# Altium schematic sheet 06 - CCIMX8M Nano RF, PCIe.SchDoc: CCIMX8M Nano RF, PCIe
size A3; PageSetup: Record=PageOptions¦CenterHorizontal=True¦CenterVertical=True¦PrintScale=0.70¦XCorrection=1.00¦YCorrection=1.00¦PrintKind=0¦BorderSize=5000000¦LeftOffset=0¦BottomOffset=0¦Orientation=2¦PaperLength=4200¦PaperWidth=2970¦Scale=100¦PaperSource=7¦PrintQuality=600¦MediaType=1¦DitherType=10¦PaperKind=A4¦PrintScaleMode=1; Author: Juan Anzola; SheetNumber: 6; SheetTotal: 21
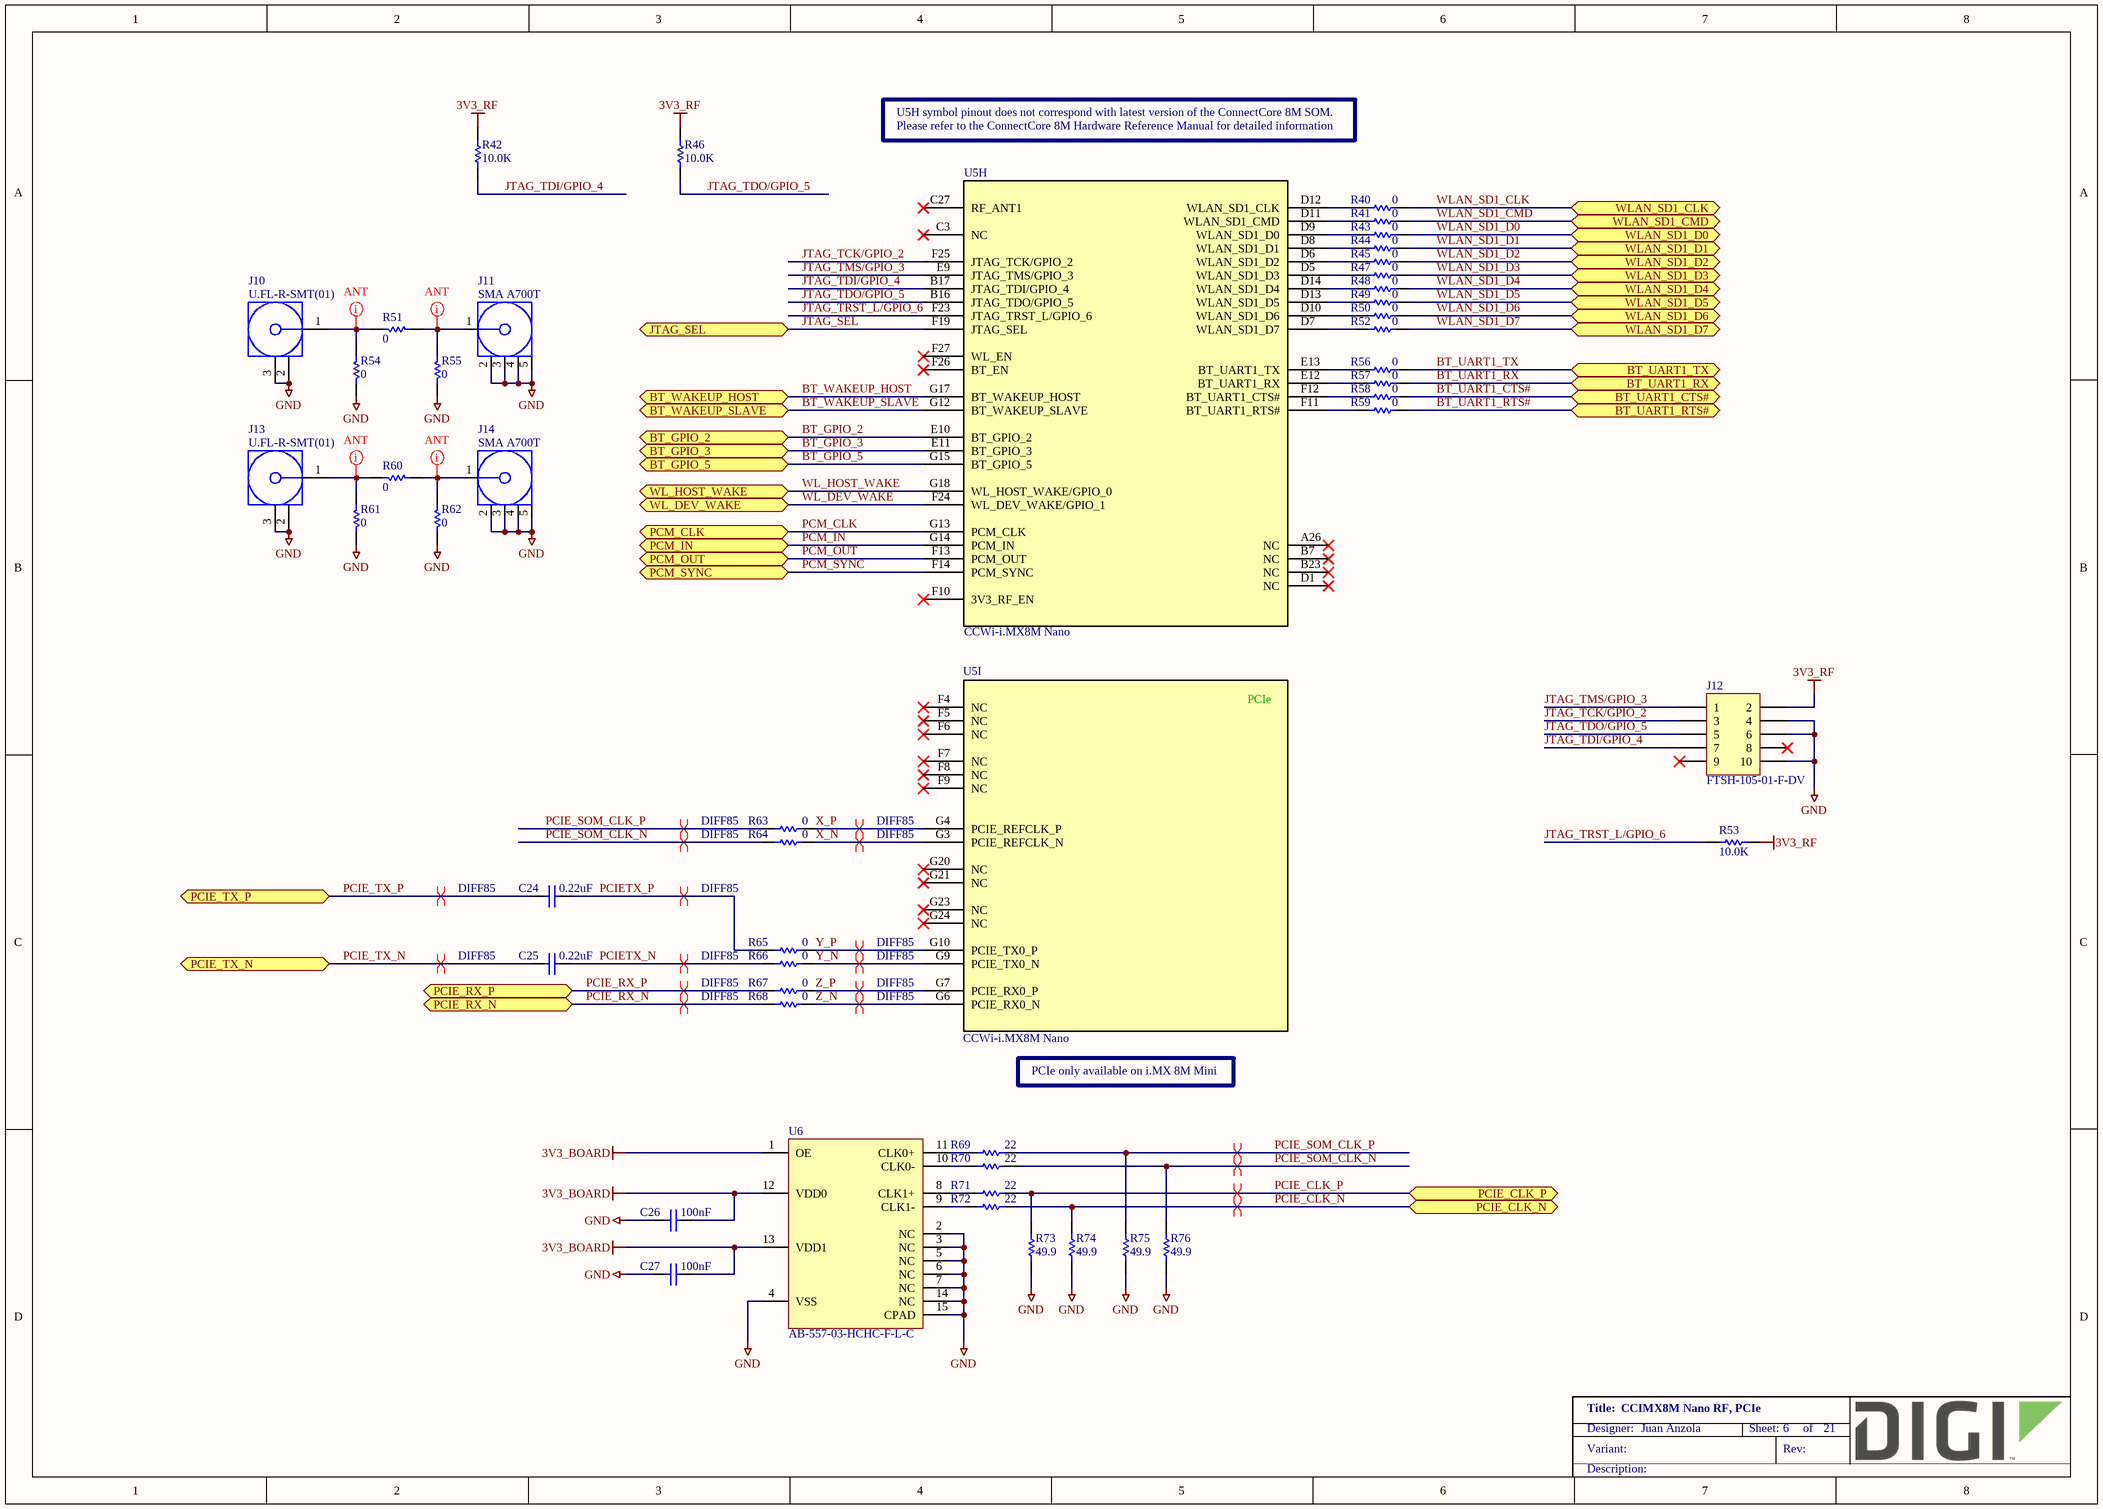
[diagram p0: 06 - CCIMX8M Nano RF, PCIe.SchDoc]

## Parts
C24  0.22uF  [CAPC1005X55N]
C25  0.22uF  [CAPC1005X55N]
C26  100nF  [CAPC1005X55N]
C27  100nF  [CAPC1005X55N]
J10  U.FL-R-SMT(01)  [HIROSE_U.FL-R-SMT(01)]
J11  SMA A700T  [BOBBINTRON_SMA A700T]
J12  FTSH-105-01-F-DV  [SAMTEC_FTSH-105-01-F-DV]
J13  U.FL-R-SMT(01)  [HIROSE_U.FL-R-SMT(01)]
J14  SMA A700T  [BOBBINTRON_SMA A700T]
R40  0  [RESC1005X40N]
R41  0  [RESC1005X40N]
R42  10.0K  [RESC1005X40N]
R43  0  [RESC1005X40N]
R44  0  [RESC1005X40N]
R45  0  [RESC1005X40N]
R46  10.0K  [RESC1005X40N]
R47  0  [RESC1005X40N]
R48  0  [RESC1005X40N]
R49  0  [RESC1005X40N]
R50  0  [RESC1005X40N]
R51  0  [RESC1005X40N]
R52  0  [RESC1005X40N]
R53  10.0K  [RESC1005X40N]
R54  0  [RESC1005X40N]
R55  0  [RESC1005X40N]
R56  0  [RESC1005X40N]
R57  0  [RESC1005X40N]
R58  0  [RESC1005X40N]
R59  0  [RESC1005X40N]
R60  0  [RESC1005X40N]
R61  0  [RESC1005X40N]
R62  0  [RESC1005X40N]
R63  0  [RESC1609X55N]
R64  0  [RESC1609X55N]
R65  0  [RESC1609X55N]
R66  0  [RESC1609X55N]
R67  0  [RESC1609X55N]
R68  0  [RESC1609X55N]
R69  22  [RESC1005X40N]
R70  22  [RESC1005X40N]
R71  22  [RESC1005X40N]
R72  22  [RESC1005X40N]
R73  49.9  [RESC1005X40N]
R74  49.9  [RESC1005X40N]
R75  49.9  [RESC1005X40N]
R76  49.9  [RESC1005X40N]
U5  CCWi-i.MX8M Nano  [E-TEC_LPJ474-129M-32ABEW55L]  (parts H,I of 10)
U6  AB-557-03-HCHC-F-L-C  [QFN50P320X250X90-15T140X210N]

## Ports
BT_GPIO_2 (bidir), BT_GPIO_3 (bidir), BT_GPIO_5 (bidir), BT_UART1_CTS# (bidir), BT_UART1_RTS# (bidir), BT_UART1_RX (bidir), BT_UART1_TX (bidir), BT_WAKEUP_HOST (bidir), BT_WAKEUP_SLAVE (bidir), JTAG_SEL (bidir), PCIE_CLK_N (bidir), PCIE_CLK_P (bidir), PCIE_RX_N (bidir), PCIE_RX_P (bidir), PCIE_TX_N (bidir), PCIE_TX_P (bidir), PCM_CLK (bidir), PCM_IN (bidir), PCM_OUT (bidir), PCM_SYNC (bidir), WL_DEV_WAKE (bidir), WL_HOST_WAKE (bidir), WLAN_SD1_CLK (bidir), WLAN_SD1_CMD (bidir), WLAN_SD1_D0 (bidir), WLAN_SD1_D1 (bidir), WLAN_SD1_D2 (bidir), WLAN_SD1_D3 (bidir), WLAN_SD1_D4 (bidir), WLAN_SD1_D5 (bidir), WLAN_SD1_D6 (bidir), WLAN_SD1_D7 (bidir)

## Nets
3V3_BOARD: C26.2 C27.2 U6.1(OE) U6.12(VDD0) U6.13(VDD1)
3V3_RF: J12.2 R42.2 R46.2 R53.2
GND: C26.1 C27.1 J10.2(GND) J10.3(GND) J11.2(GND) J11.3(GND) J11.4(GND) J11.5(GND) J12.4 J12.6 J12.10 J13.2(GND) J13.3(GND) J14.2(GND) J14.3(GND) J14.4(GND) J14.5(GND) R54.1 R55.1 R61.1 R62.1 R73.1 R74.1 R75.2 R76.2 U6.2(NC) U6.3(NC) U6.4(VSS) U6.5(NC) U6.6(NC) U6.7(NC) U6.14(NC) U6.15(CPAD)
BT_GPIO_2: U5.E10(BT_GPIO_2) ; port BT_GPIO_2
BT_GPIO_3: U5.E11(BT_GPIO_3) ; port BT_GPIO_3
BT_GPIO_5: U5.G15(BT_GPIO_5) ; port BT_GPIO_5
BT_UART1_CTS#: R58.2 ; port BT_UART1_CTS#
BT_UART1_RTS#: R59.2 ; port BT_UART1_RTS#
BT_UART1_RX: R57.2 ; port BT_UART1_RX
BT_UART1_TX: R56.2 ; port BT_UART1_TX
BT_WAKEUP_HOST: U5.G17(BT_WAKEUP_HOST) ; port BT_WAKEUP_HOST
BT_WAKEUP_SLAVE: U5.G12(BT_WAKEUP_SLAVE) ; port BT_WAKEUP_SLAVE
JTAG_SEL: U5.F19(JTAG_SEL) ; port JTAG_SEL
JTAG_TCK/GPIO_2: J12.3 U5.F25(JTAG_TCK/GPIO_2)
JTAG_TDI/GPIO_4: J12.7 R42.1 U5.B17(JTAG_TDI/GPIO_4)
JTAG_TDO/GPIO_5: J12.5 R46.1 U5.B16(JTAG_TDO/GPIO_5)
JTAG_TMS/GPIO_3: J12.1 U5.E9(JTAG_TMS/GPIO_3)
JTAG_TRST_L/GPIO_6: R53.1 U5.F23(JTAG_TRST_L/GPIO_6)
PCIE_CLK_N: R72.2 R74.2 ; port PCIE_CLK_N
PCIE_CLK_P: R71.2 R73.2 ; port PCIE_CLK_P
PCIE_RX_N: R68.1 ; port PCIE_RX_N
PCIE_RX_P: R67.1 ; port PCIE_RX_P
PCIE_SOM_CLK_N: R64.1 R70.2 R76.1
PCIE_SOM_CLK_P: R63.1 R69.2 R75.1
PCIE_TX_N: C25.2 ; port PCIE_TX_N
PCIE_TX_P: C24.2 ; port PCIE_TX_P
PCIETX_N: C25.1 R66.1
PCIETX_P: C24.1 R65.1
PCM_CLK: U5.G13(PCM_CLK) ; port PCM_CLK
PCM_IN: U5.G14(PCM_IN) ; port PCM_IN
PCM_OUT: U5.F13(PCM_OUT) ; port PCM_OUT
PCM_SYNC: U5.F14(PCM_SYNC) ; port PCM_SYNC
WL_DEV_WAKE: U5.F24(WL_DEV_WAKE/GPIO_1) ; port WL_DEV_WAKE
WL_HOST_WAKE: U5.G18(WL_HOST_WAKE/GPIO_0) ; port WL_HOST_WAKE
WLAN_SD1_CLK: R40.2 ; port WLAN_SD1_CLK
WLAN_SD1_CMD: R41.2 ; port WLAN_SD1_CMD
WLAN_SD1_D0: R43.2 ; port WLAN_SD1_D0
WLAN_SD1_D1: R44.2 ; port WLAN_SD1_D1
WLAN_SD1_D2: R45.2 ; port WLAN_SD1_D2
WLAN_SD1_D3: R47.2 ; port WLAN_SD1_D3
WLAN_SD1_D4: R48.2 ; port WLAN_SD1_D4
WLAN_SD1_D5: R49.2 ; port WLAN_SD1_D5
WLAN_SD1_D6: R50.2 ; port WLAN_SD1_D6
WLAN_SD1_D7: R52.2 ; port WLAN_SD1_D7
X_N: R64.2 U5.G3(PCIE_REFCLK_N)
X_P: R63.2 U5.G4(PCIE_REFCLK_P)
Y_N: R66.2 U5.G9(PCIE_TX0_N)
Y_P: R65.2 U5.G10(PCIE_TX0_P)
Z_N: R68.2 U5.G6(PCIE_RX0_N)
Z_P: R67.2 U5.G7(PCIE_RX0_P)
NetJ10_1: J10.1(Signal) R51.2 R54.2
NetJ11_1: J11.1(Signal) R51.1 R55.2
NetJ13_1: J13.1(Signal) R60.2 R61.2
NetJ14_1: J14.1(Signal) R60.1 R62.2
NetR40_1: R40.1 U5.D12(WLAN_SD1_CLK)
NetR41_1: R41.1 U5.D11(WLAN_SD1_CMD)
NetR43_1: R43.1 U5.D9(WLAN_SD1_D0)
NetR44_1: R44.1 U5.D8(WLAN_SD1_D1)
NetR45_1: R45.1 U5.D6(WLAN_SD1_D2)
NetR47_1: R47.1 U5.D5(WLAN_SD1_D3)
NetR48_1: R48.1 U5.D14(WLAN_SD1_D4)
NetR49_1: R49.1 U5.D13(WLAN_SD1_D5)
NetR50_1: R50.1 U5.D10(WLAN_SD1_D6)
NetR52_1: R52.1 U5.D7(WLAN_SD1_D7)
NetR56_1: R56.1 U5.E13(BT_UART1_TX)
NetR57_1: R57.1 U5.E12(BT_UART1_RX)
NetR58_1: R58.1 U5.F12(BT_UART1_CTS#)
NetR59_1: R59.1 U5.F11(BT_UART1_RTS#)
NetR69_1: R69.1 U6.11(CLK0+)
NetR70_1: R70.1 U6.10(CLK0-)
NetR71_1: R71.1 U6.8(CLK1+)
NetR72_1: R72.1 U6.9(CLK1-)

Not connected (* = marked no-connect by the designer): J12 8* 9*; U5 A26(NC)* B7(NC)* B23(NC)* C3(NC)* C27(RF_ANT1)* D1(NC)* F4(NC)* F5(NC)* F6(NC)* F7(NC)* F8(NC)* F9(NC)* F10(3V3_RF_EN)* F26(BT_EN)* F27(WL_EN)* G20(NC)* G21(NC)* G23(NC)* G24(NC)*

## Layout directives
differential pair; net class DIFF85: PCIE_RX_N, PCIE_RX_P, PCIE_SOM_CLK_N, PCIE_SOM_CLK_P, PCIE_TX_N, PCIE_TX_P, PCIETX_N, PCIETX_P, X_N, X_P, Y_N, Y_P, Z_N, Z_P
differential pair: PCIE_CLK_N, PCIE_CLK_P, PCIE_SOM_CLK_N, PCIE_SOM_CLK_P
net class ANT: NetJ10_1, NetJ11_1, NetJ13_1, NetJ14_1

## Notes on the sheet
- U5H symbol pinout does not correspond with latest version of the ConnectCore 8M SOM.
- Please refer to the ConnectCore 8M Hardware Reference Manual for detailed information
- PCIe only available on i.MX 8M Mini

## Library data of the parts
C24 C25 = 1001883: CAP CER 0.22UF 6.3V X7R 0402; Part_Type: Capacitor; Manufacturer: Taiyo Yuden; Manufacturer_Part_Number: JMK105B7224KV-F; Digi_PN: 14000067; Component_Life_Cycle_State: Reviewed; Area: 2.2; Project: Powerley Energy Bridge; Tolerance: 10%
C26 C27 = 1000006: CAP 100nF 16V 10% X7R 0402; Part_Type: Capacitor; Manufacturer: Murata; Manufacturer_Part_Number: GRM155R71C104KA88D; Digi_PN: 14050552; Component_Life_Cycle_State: CAD Reviewed; Area: 0.95; Project: KITT; Tolerance: 10
J10 J13 = 1000027: RF Connectors U.FL RECEPTACLE SMT GLD M CONTACT; Manufacturer: Hirose; Digi_PN: 18000684; Component_Life_Cycle_State: Proven; Area: 14,4
J11 J14 = 1002720: CONN SMA JACK R/A 50 OHM L15.1MM PCB TH; Part_Type: Connector; Manufacturer: Bobbintron Electrical Corp; Digi_PN: MA02979; Component_Life_Cycle_State: Reviewed; Area: 121,68
J12 = 1000034: CONN HEADER 10POS DUAL .05" SMD; Part_Type: Connector; Manufacturer: Samtec; Note: 18000715 = Digi No. for GE WDNU; Digi_PN: 18000539; Component_Life_Cycle_State: Proven; Area: 43,55
R40 R41 R43-R45 R47-R50 R52 R56-R59 = 1000076: RES 0.0 OHM 1/10W 0402 SMD; Part_Type: Resistor; Manufacturer: Panasonic - ECG; Manufacturer_Part_Number: ERJ-2GE0R00X; Component_Life_Cycle_State: Proven; Area: 0.95; Project: Adjustable Foundation; Power_WV_SRF: 10; Digi_PN: 13050387
R42 R46 R53 = 1000537: RES 10.0K OHM 1/10W 1% 0402 SMD; Part_Type: Resistor; Manufacturer: Panasonic - ECG; Manufacturer_Part_Number: ERJ-2RKF1002X; Digi_PN: 13051084; Component_Life_Cycle_State: CAD Reviewed; Area: 0,95; Power_WV_SRF: 100
R51 R54 R55 R60-R62 = 1000076: RES 0.0 OHM 1/10W 0402 SMD; Part_Type: Resistor; Manufacturer: Panasonic - ECG; Manufacturer_Part_Number: ERJ-2GE0R00X; Digi_PN: 13050387; Component_Life_Cycle_State: Proven; Area: 0,95; Project: Adjustable Foundation; Power_WV_SRF: 10
R63-R68 = 1000208: RES 0.0 OHM 1/10W 0603; Part_Type: Resistor; Manufacturer: Panasonic - ECG; Manufacturer_Part_Number: ERJ-3GEY0R00V; Note: 13051103 = Digi No. for GE WDNU; Digi_PN: 13050568; Component_Life_Cycle_State: Reviewed; Area: 2,5; Voltage: 75V
R69-R72 = 1000601: RES 22.0 OHM 1/10W 1% 0402 SMD; Part_Type: Resistor; Manufacturer: Panasonic - ECG; Manufacturer_Part_Number: ERJ-2RKF22R0X; Digi_PN: 13051089; Component_Life_Cycle_State: CAD Reviewed; Area: 0.95; Project: KITT; Power_WV_SRF: 100
R73-R76 = 1000466: RES 49.9 OHM 1/10W 1% 0402 SMD; Part_Type: Resistor; Manufacturer: Panasonic - ECG; Manufacturer_Part_Number: ERJ-2RKF49R9X; Digi_PN: 13051083; Component_Life_Cycle_State: CAD Reviewed; Area: 0.95; Project: KITT; Power_WV_SRF: 100
U5 = 1002739: ConnectCore for i.MX8M Nano module - LGA; Manufacturer: DIGI; Digi_PN: 50002014-01; Component_Life_Cycle_State: Pending
U6 = 1002449: SMIC PCIE CLOCK GEN 100MHZ 14QFN; Part_Type: IC; Manufacturer: Abracon Corporation; Digi_PN: 16000101; Component_Life_Cycle_State: Created; Area: 16; Project: DIGI CC8X SOM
